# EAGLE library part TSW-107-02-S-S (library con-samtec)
THROUGH-HOLE .025" SQ POST HEADER Source: Samtec TSW.pdf
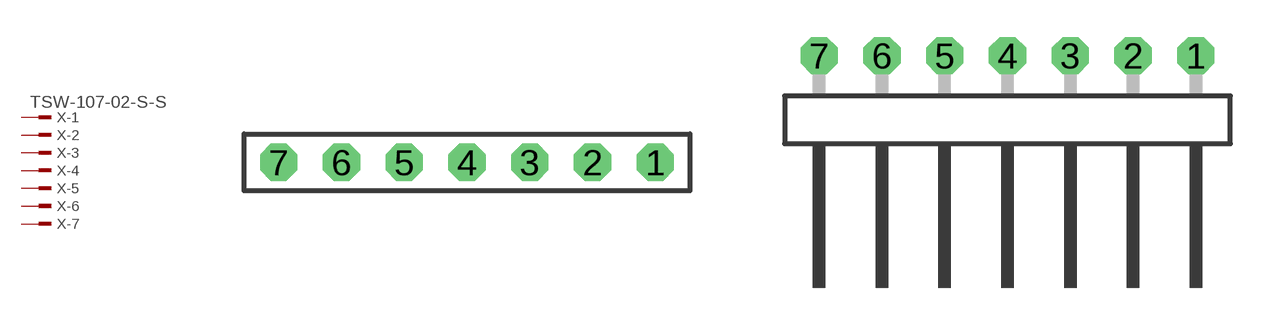
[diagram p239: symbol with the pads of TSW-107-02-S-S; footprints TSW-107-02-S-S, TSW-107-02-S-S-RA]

Designator prefix X; gates -1=MPINV -2=MPIN -3=MPIN -4=MPIN -5=MPIN -6=MPIN -7=MPIN

## TSW-107-02-S-S (OC_FARNELL: unknown; OC_NEWARK: unknown)  [TSW-107-02-S-S]
1  -1:1  pas
2  -2:1  pas
3  -3:1  pas
4  -4:1  pas
5  -5:1  pas
6  -6:1  pas
7  -7:1  pas

## TSW-107-02-S-S-RA (OC_FARNELL: unknown; OC_NEWARK: unknown)  [TSW-107-02-S-S-RA]
Pads as for TSW-107-02-S-S

## Footprint TSW-107-02-S-S (pad centres in mm)
THROUGH-HOLE .025" SQ POST HEADER Source: Samtec TSW.pdf
drill 1 pad 1.5 octagon: 1 7.62,0; 2 5.08,0; 3 2.54,0; 4 0,0; 5 -2.54,0; 6 -5.08,0; 7 -7.62,0

## Footprint TSW-107-02-S-S-RA (pad centres in mm)
THROUGH-HOLE .025" SQ POST HEADER Source: Samtec TSW.pdf
drill 1 pad 1.5 octagon: 1 7.62,1.524; 2 5.08,1.524; 3 2.54,1.524; 4 0,1.524; 5 -2.54,1.524; 6 -5.08,1.524; 7 -7.62,1.524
